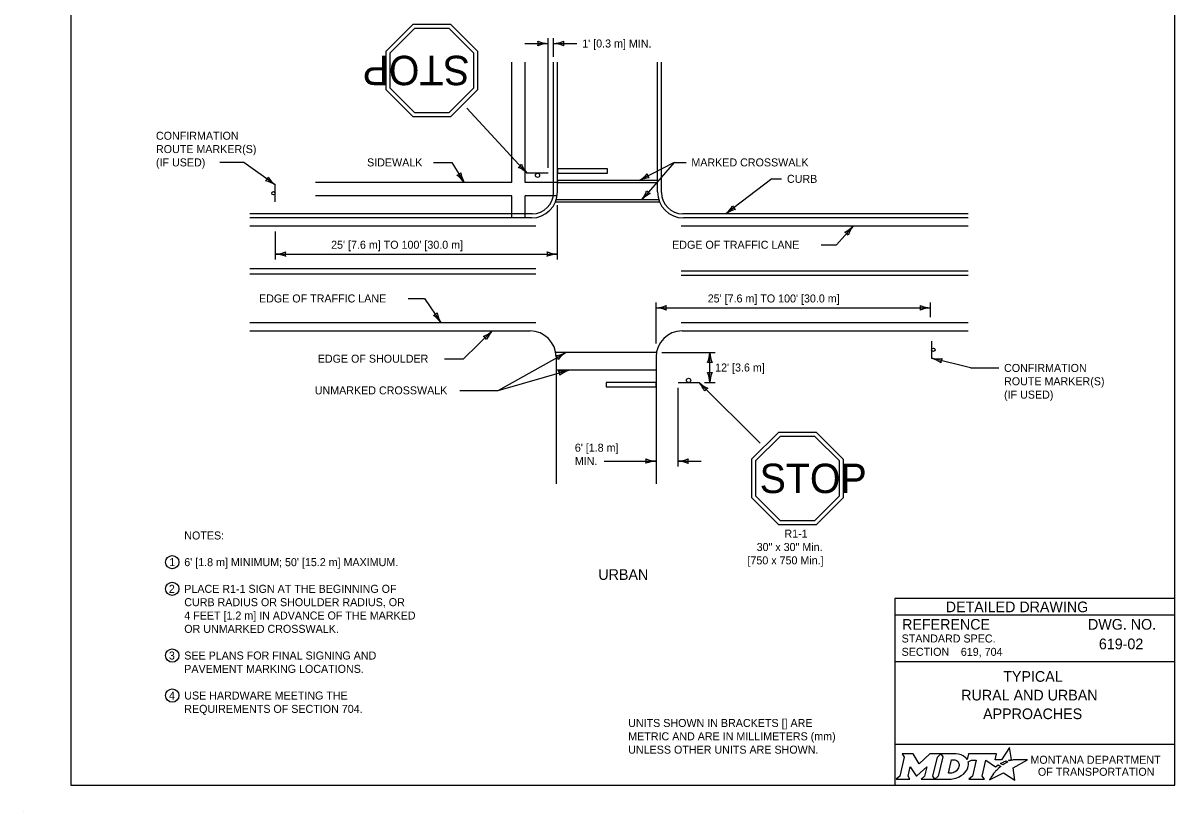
# Model space of a CAD drawing. Extents: x 49991.4 to 50021, y 49987.6 to 50011.4.
# Drawn here: x 49999.98 to 50008.61, y 49999.86 to 50005.78 of the extents above; entities that cross this region are included whole.
import ezdxf

# ---------------------------------------------------------------- set-up
doc = ezdxf.new("R2010")
doc.units = 0
for name, color, linetype in [('Level 1', 7, 'Continuous'), ('Level 2', 7, 'Continuous'), ('Level 3', 7, 'Continuous')]:
    doc.layers.add(name, color=color, linetype=linetype)

# ---------------------------------------------------------------- blocks, each defined once
blk = doc.blocks.new('ARR')
at = {"layer": 'Level 3'}
for centre, radius, start, end in [((1.5, 37), 37.1, 247.4737, 267.6572), ((-21.4, 0), 9.13, 342.1565, 17.8788), ((1.9, -38.8), 38.8, 92.845, 112.0948)]:
    blk.add_arc(centre, radius, start, end, dxfattribs=at)
blk = doc.blocks.new('ARROW')
at = {"layer": 'Level 3', "xscale": 0.9999534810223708, "yscale": 0.999953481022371, "rotation": -0.017609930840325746}
blk.add_blockref('ARR', (-0.0303, -0.0431), dxfattribs=at)

msp = doc.modelspace()

# ---------------------------------------------------------------- linework, layer by layer
at = {"layer": 'Level 1'}
for p, q in [((50002.8988, 50005.7665), (50002.697, 50005.5647)), ((50002.9113, 50005.7365), (50002.727, 50005.5522)), ((50003.1846, 50005.7665), (50002.8988, 50005.7665)), ((50003.172, 50005.7365), (50002.9113, 50005.7365)), ((50003.172, 50005.7365), (50003.3563, 50005.5522)), ((50003.1846, 50005.7665), (50003.3863, 50005.5648)), ((50002.697, 50005.5647), (50002.697, 50005.2791)), ((50003.3863, 50005.279), (50003.3863, 50005.5648)), ((50002.727, 50005.5522), (50002.727, 50005.2915)), ((50003.3563, 50005.2915), (50003.3563, 50005.5522)), ((50003.6422, 50004.5813), (50003.6422, 50005.4852)), ((50003.7422, 50004.5813), (50003.7422, 50005.4852)), ((50003.9542, 50004.5066), (50003.9542, 50005.4852)), ((50003.9842, 50004.512), (50003.9842, 50005.4852)), ((50004.7342, 50004.5119), (50004.7342, 50005.4851)), ((50004.7642, 50004.5066), (50004.7642, 50005.4852)), ((50002.8989, 50005.0772), (50002.697, 50005.2791)), ((50002.9113, 50005.1072), (50002.727, 50005.2915)), ((50003.172, 50005.1072), (50003.3563, 50005.2915)), ((50003.1845, 50005.0772), (50003.3863, 50005.279)), ((50002.8989, 50005.0772), (50003.1845, 50005.0772)), ((50002.9113, 50005.1072), (50003.172, 50005.1072)), ((50003.9137, 50004.6516), (50003.7555, 50004.6516)), ((50004.3592, 50004.6836), (50003.9842, 50004.6836)), ((50003.9842, 50004.6836), (50003.9842, 50004.6516)), ((50003.9842, 50004.6516), (50004.3592, 50004.6516)), ((50004.3592, 50004.6516), (50004.3592, 50004.6836)), ((50001.8667, 50004.4381), (50001.8667, 50004.5647)), ((50003.6422, 50004.5813), (50002.1694, 50004.5813)), ((50003.9842, 50004.5813), (50003.7422, 50004.5813)), ((50004.7342, 50004.5963), (50003.9842, 50004.5963)), ((50003.9842, 50004.5963), (50003.9842, 50004.5813)), ((50003.9842, 50004.5813), (50004.7342, 50004.5813)), ((50004.7342, 50004.5813), (50004.7342, 50004.5963)), ((50003.6422, 50004.4813), (50002.1694, 50004.4813)), ((50003.6422, 50004.3167), (50003.6422, 50004.4813)), ((50003.7422, 50004.3167), (50003.7422, 50004.4813)), ((50003.9818, 50004.4813), (50003.7422, 50004.4813)), ((50003.9692, 50004.4367), (50004.7493, 50004.4367)), ((50004.7438, 50004.4517), (50003.9747, 50004.4517)), ((50003.7942, 50004.3466), (50001.6775, 50004.3466)), ((50007.0628, 50004.3466), (50004.9242, 50004.3466)), ((50003.7889, 50004.3167), (50001.6775, 50004.3167)), ((50007.0628, 50004.3166), (50004.9296, 50004.3166)), ((50003.8222, 50004.2541), (50001.6775, 50004.2541)), ((50007.0628, 50004.2541), (50004.9128, 50004.2541)), ((50003.8222, 50003.9347), (50001.6775, 50003.9347)), ((50007.0628, 50003.9178), (50004.9128, 50003.9178)), ((50003.8222, 50003.8954), (50001.6775, 50003.8954)), ((50007.0628, 50003.8856), (50004.9128, 50003.8856)), ((50001.6775, 50003.5316), (50003.8222, 50003.5316)), ((50004.9128, 50003.5316), (50007.0628, 50003.5316)), ((50001.6775, 50003.4691), (50003.7783, 50003.4691)), ((50004.919, 50003.4691), (50007.0628, 50003.4691)), ((50006.79, 50003.3913), (50006.79, 50003.2648)), ((50004.7266, 50003.3073), (50003.9708, 50003.3073)), ((50003.9737, 50003.2738), (50003.9737, 50002.323)), ((50004.7237, 50003.2738), (50004.7237, 50002.3229)), ((50004.7237, 50003.1738), (50003.9737, 50003.1738)), ((50004.7237, 50003.0822), (50004.3487, 50003.0823)), ((50004.3487, 50003.0823), (50004.3487, 50003.0503)), ((50004.3487, 50003.0503), (50004.7237, 50003.0502)), ((50004.7237, 50003.0502), (50004.7237, 50003.0822)), ((50004.8882, 50003.0822), (50005.0465, 50003.0822)), ((50005.6415, 50002.7081), (50005.4397, 50002.5063)), ((50005.9271, 50002.7081), (50005.6415, 50002.7081)), ((50005.9271, 50002.7081), (50006.129, 50002.5062)), ((50005.654, 50002.6781), (50005.4697, 50002.4938)), ((50005.9147, 50002.6781), (50005.654, 50002.6781)), ((50005.9147, 50002.6781), (50006.099, 50002.4938)), ((50005.4397, 50002.5063), (50005.4397, 50002.2205)), ((50005.4697, 50002.4938), (50005.4697, 50002.2331)), ((50006.099, 50002.2331), (50006.099, 50002.4938)), ((50006.129, 50002.2206), (50006.129, 50002.5062)), ((50005.6414, 50002.0188), (50005.4397, 50002.2205)), ((50005.654, 50002.0488), (50005.4697, 50002.2331)), ((50005.9147, 50002.0488), (50006.099, 50002.2331)), ((50005.9272, 50002.0188), (50006.129, 50002.2206)), ((50005.6414, 50002.0188), (50005.9272, 50002.0188)), ((50005.654, 50002.0488), (50005.9147, 50002.0488)), ((49999.9766, 49999.8624), (49999.9766, 49999.8624))]:
    msp.add_line(p, q, dxfattribs=at)
msp.add_lwpolyline([(50008.6146, 50011.2628), (50000.3356, 50011.2628), (50000.3356, 50000.0624), (50008.6146, 50000.0624)], close=True, dxfattribs=at)
for centre, radius in [((50003.8346, 50004.6358), 0.0158), ((50001.854, 50004.5013), 0.0127), ((50006.8027, 50003.3281), 0.0127), ((50004.9673, 50003.0981), 0.0159)]:
    msp.add_circle(centre, radius, dxfattribs=at)
for centre, radius, start, end in [((50003.7889, 50004.512), 0.1953, 270, 0), ((50003.7942, 50004.5066), 0.16, 270, 0), ((50003.7889, 50004.5119), 0.1953, 337.34235, 342.03572), ((50004.9296, 50004.5119), 0.1953, 180, 270), ((50004.9296, 50004.5119), 0.1953, 197.96428, 202.65765), ((50004.9242, 50004.5066), 0.16, 180, 270), ((50003.7783, 50003.2738), 0.1953, 0, 90), ((50004.919, 50003.2738), 0.1953, 90, 180)]:
    msp.add_arc(centre, radius, start, end, dxfattribs=at)
at = {"layer": 'Level 2'}
for p, q in [((50008.6146, 50001.4624), (50006.5146, 50001.4624)), ((50006.5146, 50001.4624), (50006.5146, 50000.0624)), ((50008.6146, 50001.3374), (50006.5146, 50001.3374)), ((50008.2507, 50001.1223), (50008.2507, 50001.1223)), ((50008.6146, 50000.9874), (50006.5146, 50000.9874)), ((50007.0089, 50001.0629), (50007.0089, 50001.0629)), ((50007.5646, 50000.7383), (50007.5646, 50000.7383)), ((50008.6146, 50000.3693), (50006.5146, 50000.3693))]:
    msp.add_line(p, q, dxfattribs=at)
for points in [[(50006.5701, 50000.2974), (50006.5842, 50000.274), (50006.5507, 50000.1307), (50006.525, 50000.1082), (50006.6266, 50000.1082), (50006.6131, 50000.131), (50006.6293, 50000.2011), (50006.673, 50000.1321), (50006.6783, 50000.1321), (50006.7534, 50000.2016), (50006.737, 50000.1305), (50006.7123, 50000.1085), (50006.8139, 50000.1085), (50006.8001, 50000.1318), (50006.8333, 50000.2742)], [(50006.8333, 50000.2742), (50006.8586, 50000.2974), (50006.7762, 50000.2974), (50006.6966, 50000.2244), (50006.6521, 50000.2971), (50006.5701, 50000.2974)], [(50006.9722, 50000.2974), (50006.8586, 50000.2974), (50006.8733, 50000.2745), (50006.8394, 50000.1307), (50006.8139, 50000.1085), (50006.9245, 50000.1085)], [(50007.3771, 50000.2447), (50007.3668, 50000.2503), (50007.3784, 50000.2531), (50007.39, 50000.2551), (50007.3726, 50000.3452), (50007.3131, 50000.2539), (50007.2658, 50000.2532), (50007.2761, 50000.2973), (50007.0669, 50000.2974), (50007.0568, 50000.2549), (50007.051, 50000.2632)], [(50006.9962, 50000.2107), (50006.995, 50000.2026), (50006.9918, 50000.1933), (50006.9876, 50000.1851), (50006.982, 50000.1776), (50006.9755, 50000.1707), (50006.9676, 50000.1644), (50006.9593, 50000.1597), (50006.9502, 50000.1558), (50006.9411, 50000.1535), (50006.9319, 50000.1526), (50006.916, 50000.1526), (50006.9396, 50000.2526), (50006.9556, 50000.2526), (50006.9632, 50000.252), (50006.9708, 50000.2501), (50006.9774, 50000.2471), (50006.9835, 50000.2429), (50006.9883, 50000.2379), (50006.992, 50000.2319), (50006.9947, 50000.2257), (50006.9963, 50000.2183), (50006.9963, 50000.2153), (50006.9962, 50000.2107)], [(50007.0636, 50000.2383), (50007.0882, 50000.2514), (50007.1251, 50000.2514), (50007.0965, 50000.1309), (50007.069, 50000.1082), (50007.1852, 50000.1082), (50007.1682, 50000.1311), (50007.1964, 50000.2513), (50007.2677, 50000.1996), (50007.2888, 50000.2147), (50007.3085, 50000.2038)], [(50007.2527, 50000.1479), (50007.2374, 50000.1235), (50007.2327, 50000.116), (50007.2269, 50000.1074), (50007.2246, 50000.1031), (50007.3299, 50000.1562), (50007.4138, 50000.1011), (50007.4007, 50000.1938), (50007.5076, 50000.2522), (50007.4583, 50000.253), (50007.4282, 50000.2534), (50007.4074, 50000.2537), (50007.4006, 50000.2522), (50007.3957, 50000.251), (50007.3873, 50000.2487), (50007.3771, 50000.2447)], [(50007.3267, 50000.2171), (50007.3243, 50000.2154), (50007.306, 50000.225), (50007.3163, 50000.2307), (50007.3204, 50000.2329), (50007.329, 50000.2369), (50007.3347, 50000.2395), (50007.3426, 50000.2425), (50007.3499, 50000.2452), (50007.3617, 50000.2378), (50007.3577, 50000.2357), (50007.3531, 50000.2332), (50007.3489, 50000.231), (50007.3439, 50000.2281), (50007.342, 50000.227), (50007.3393, 50000.2254), (50007.3368, 50000.224), (50007.3345, 50000.2224), (50007.3319, 50000.2206), (50007.3292, 50000.2188), (50007.3267, 50000.2171)], [(50006.9702, 50000.1158), (50006.9786, 50000.1184), (50006.9916, 50000.1238), (50007.012, 50000.1348)], [(50007.2666, 50000.164), (50007.2666, 50000.164)]]:
    msp.add_lwpolyline(points, dxfattribs=at)
for centre in [(50001.0956, 50001.7353), (50001.0956, 50001.5353), (50001.0956, 50001.0353), (50001.0956, 50000.7353)]:
    msp.add_circle(centre, 0.05, dxfattribs=at)
for centre, radius, start, end in [((50006.9953, 50000.219), 0.0709, 339.53292, 15.85821), ((50006.9513, 50000.2363), 0.1183, 300.91025, 339.13831)]:
    msp.add_arc(centre, radius, start, end, dxfattribs=at)
for centre, major_axis, ratio, start_param, end_param in [((50006.9701, 50000.25), (0.0834, -0.0037), 0.568097, 0.61298, 1.570796), ((50007.0257, 50000.2573), (0.0361, -0.0295), 0.469099, 1.225588, 1.570796), ((50007.2974, 50000.1941), (-0.0112, -0.0097), 0.021651, 3.157348, 6.283185), ((50006.9248, 50000.2568), (0, 0.1484), 0.987302, 3.139398, 3.456847), ((50007.2597, 50000.1559), (-0.00694, -0.00806), 0.008222, 0, 3.137361), ((50007.2764, 50000.1742), (-0.0098, -0.0102), 0.016458, 3.141593, 6.279097)]:
    msp.add_ellipse(centre, major_axis=major_axis, ratio=ratio, start_param=start_param, end_param=end_param, dxfattribs=at)
at = {"layer": 'Level 3'}
for p, q in [((50003.9137, 50004.6916), (50003.9137, 50005.664)), ((50003.9542, 50005.5252), (50003.9542, 50005.664)), ((50003.7403, 50005.624), (50003.9137, 50005.624)), ((50003.9542, 50005.624), (50004.13, 50005.624)), ((50003.3036, 50005.1398), (50003.7555, 50004.6516)), ((50001.6329, 50004.7325), (50001.4529, 50004.7325)), ((50001.8667, 50004.5647), (50001.6329, 50004.7325)), ((50003.0534, 50004.7325), (50003.1908, 50004.7325)), ((50003.1908, 50004.7325), (50003.285, 50004.5813)), ((50004.8589, 50004.7325), (50004.5967, 50004.5963)), ((50004.8589, 50004.7325), (50004.6158, 50004.4517)), ((50004.8589, 50004.7325), (50004.9483, 50004.7325)), ((50005.5905, 50004.6093), (50005.2475, 50004.3466)), ((50005.5905, 50004.6093), (50005.665, 50004.6093)), ((50003.9842, 50004.0051), (50003.9842, 50004.412)), ((50001.8687, 50004.0051), (50001.8687, 50004.2141)), ((50006.076, 50004.1151), (50006.2014, 50004.2541)), ((50005.9623, 50004.1151), (50006.076, 50004.1151)), ((50001.8687, 50004.0451), (50003.9842, 50004.0451)), ((50002.8643, 50003.7124), (50002.9877, 50003.7124)), ((50002.9877, 50003.7124), (50003.1098, 50003.5316)), ((50004.7237, 50003.3738), (50004.7237, 50003.6824)), ((50006.7817, 50003.5723), (50006.7817, 50003.6824)), ((50004.7237, 50003.6424), (50006.7817, 50003.6424)), ((50003.2796, 50003.2608), (50003.4954, 50003.4691)), ((50003.1364, 50003.2608), (50003.2796, 50003.2608)), ((50003.5402, 50003.0224), (50004.0483, 50003.3073)), ((50004.7666, 50003.3073), (50005.1665, 50003.3073)), ((50005.1265, 50003.0822), (50005.1265, 50003.3073)), ((50007.0816, 50003.1915), (50006.79, 50003.2648)), ((50003.5402, 50003.0224), (50004.0701, 50003.1738)), ((50007.0816, 50003.1915), (50007.2931, 50003.1915)), ((50005.0465, 50003.0822), (50005.5048, 50002.6279)), ((50005.0865, 50003.0822), (50005.1665, 50003.0822)), ((50003.2531, 50003.0224), (50003.5402, 50003.0224)), ((50004.8876, 50003.0422), (50004.8876, 50002.4527)), ((50004.3339, 50002.4935), (50004.7237, 50002.4935)), ((50004.8876, 50002.4927), (50005.061, 50002.4927))]:
    msp.add_line(p, q, dxfattribs=at)
for centre, radius, start, end in [((50003.9229, 50005.8461), 0.2223, 247.45601, 267.63952), ((50003.7855, 50005.624), 0.0548, 342.13882, 17.86118), ((50003.9252, 50005.3913), 0.233, 92.82731, 112.07716), ((50003.9427, 50005.8567), 0.233, 272.82731, 292.07716), ((50003.945, 50005.4019), 0.2223, 67.45601, 87.63952), ((50004.0824, 50005.624), 0.0548, 162.13882, 197.86118), ((50003.6667, 50004.7441), 0.0548, 295.96133, 331.68369), ((50003.5956, 50004.4822), 0.233, 46.64982, 65.89967), ((50003.9221, 50004.7988), 0.2223, 201.27852, 221.46203), ((50001.7625, 50004.6395), 0.0548, 306.47458, 342.19694), ((50002.0037, 50004.7398), 0.2223, 211.79177, 231.97528), ((50003.2172, 50004.6901), 0.0548, 284.05672, 319.77908), ((50003.0935, 50004.4485), 0.233, 34.74521, 53.99506), ((50003.4784, 50004.691), 0.2223, 189.37391, 209.55742), ((50001.7404, 50004.3689), 0.233, 57.16307, 76.41292), ((50005.0969, 50004.5244), 0.233, 310.27394, 329.52379), ((50005.3753, 50004.1647), 0.2223, 104.90264, 125.08615), ((50005.3493, 50004.4246), 0.0548, 199.58545, 235.30781), ((50006.0426, 50004.4097), 0.2223, 295.39808, 315.58159), ((50006.1155, 50004.1589), 0.0548, 30.08089, 65.80325), ((50006.3819, 50004.1067), 0.233, 140.76938, 160.01923), ((50001.8572, 50004.2778), 0.233, 272.82731, 292.07716), ((50001.8595, 50003.823), 0.2223, 67.45601, 87.63952), ((50001.9969, 50004.0451), 0.0548, 162.13882, 197.86118), ((50003.9934, 50004.2672), 0.2223, 247.45601, 267.63952), ((50003.856, 50004.0451), 0.0548, 342.13882, 17.86118), ((50003.9957, 50003.8124), 0.233, 92.82731, 112.07716), ((50004.7122, 50003.8751), 0.233, 272.82731, 292.07716), ((50004.8519, 50003.6424), 0.0548, 162.13882, 197.86118), ((50006.7909, 50003.8645), 0.2223, 247.45601, 267.63952), ((50006.6535, 50003.6424), 0.0548, 342.13882, 17.86118), ((50003.0386, 50003.6382), 0.0548, 285.86814, 321.5905), ((50002.9226, 50003.3928), 0.233, 36.55663, 55.80648), ((50003.2996, 50003.6473), 0.2223, 191.18533, 211.36884), ((50004.7145, 50003.4203), 0.2223, 67.45601, 87.63952), ((50006.7932, 50003.4097), 0.233, 92.82731, 112.07716), ((50003.3477, 50003.6352), 0.2223, 291.44896, 311.63247), ((50003.4031, 50003.38), 0.0548, 26.13177, 61.85413), ((50003.6653, 50003.3096), 0.233, 136.82026, 156.07011), ((50003.9476, 50003.5055), 0.2223, 276.7357, 296.91921), ((50003.9365, 50003.2446), 0.0548, 11.41851, 47.14087), ((50004.1721, 50003.1099), 0.233, 122.107, 141.35685), ((50004.9044, 50003.3165), 0.2223, 337.45601, 357.63952), ((50005.1265, 50003.1791), 0.0548, 72.13882, 107.86118), ((50005.3592, 50003.3188), 0.233, 182.82731, 202.07716), ((50006.7238, 50003.0526), 0.2223, 52.49735, 72.68085), ((50006.839, 50003.4926), 0.233, 257.86865, 277.1185), ((50006.9139, 50003.2317), 0.0548, 147.18015, 182.90252), ((50004.0179, 50003.3899), 0.2223, 263.40141, 283.58492), ((50003.9468, 50003.1386), 0.0548, 358.08422, 33.80658), ((50004.1451, 50002.9532), 0.233, 108.77271, 128.02256), ((50005.1265, 50003.2104), 0.0548, 252.13882, 287.86118), ((50004.8938, 50003.0707), 0.233, 2.82731, 22.07716), ((50005.3486, 50003.073), 0.2223, 157.45601, 177.63952), ((50004.882, 50002.9326), 0.2223, 22.09386, 42.27737), ((50005.204, 50003.2539), 0.233, 227.46516, 246.71501), ((50005.1366, 50002.991), 0.0548, 116.77667, 152.49903), ((50004.7329, 50002.7156), 0.2223, 247.45601, 267.63952), ((50004.5955, 50002.4935), 0.0548, 342.13882, 17.86118), ((50004.7352, 50002.2608), 0.233, 92.82731, 112.07716)]:
    msp.add_arc(centre, radius, start, end, dxfattribs=at)

# ---------------------------------------------------------------- block references
for p, xscale, yscale, rotation in [((50004.5967, 50004.596), 0.005999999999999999, 0.005999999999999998, -152.55038653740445), ((50004.6159, 50004.4514), 0.005999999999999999, 0.006, -130.88411671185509), ((50004.8874, 50002.4924), 0.006, 0.006, 180)]:
    msp.add_blockref('ARROW', p, dxfattribs=dict(at, xscale=xscale, yscale=yscale, rotation=rotation))

# ---------------------------------------------------------------- texts
at = {"layer": 'Level 1'}
for rotation, p in [(180, (50003.3256, 50005.5321)), (360, (50005.5004, 50002.2532))]:
    msp.add_text('STOP', height=0.2205, rotation=rotation, dxfattribs=at).set_placement(p)
at = {"layer": 'Level 2'}
for s, height, p in [("1' [0.3 m] MIN.", 0.06, (50004.17, 50005.594)), ('CONFIRMATION', 0.06, (50000.9735, 50004.9025)), ('ROUTE MARKER(S)', 0.06, (50000.9735, 50004.8025)), ('(IF USED)', 0.06, (50000.9735, 50004.7025)), ('SIDEWALK', 0.06, (50002.5566, 50004.7025)), ('MARKED CROSSWALK', 0.06, (50004.9883, 50004.7025)), ('CURB', 0.06, (50005.705, 50004.5793)), ("25' [7.6 m] TO 100' [30.0 m]", 0.06, (50002.2867, 50004.0851)), ('EDGE OF TRAFFIC LANE', 0.06, (50004.8441, 50004.0851)), ('EDGE OF TRAFFIC LANE', 0.06, (50001.7461, 50003.6824)), ("25' [7.6 m] TO 100' [30.0 m]", 0.06, (50005.1108, 50003.6824)), ('EDGE OF SHOULDER', 0.06, (50002.1867, 50003.2308)), ("12' [3.6 m]", 0.06, (50005.1665, 50003.1648)), ('CONFIRMATION', 0.06, (50007.3331, 50003.1615)), ('UNMARKED CROSSWALK', 0.06, (50002.1642, 50002.9934)), ('ROUTE MARKER(S)', 0.06, (50007.3331, 50003.0615)), ('(IF USED)', 0.06, (50007.3331, 50002.9615)), ("6' [1.8 m]", 0.06, (50004.1143, 50002.5635)), ('MIN.', 0.06, (50004.1143, 50002.4635)), ('NOTES:', 0.06, (50001.1856, 50001.9053)), ('R1-1', 0.06, (50005.686, 50001.9188)), ('30" x 30" Min.', 0.06, (50005.4779, 50001.8188)), ('1', 0.06, (50001.0729, 50001.7053)), ("6' [1.8 m] MINIMUM; 50' [15.2 m] MAXIMUM.", 0.06, (50001.1856, 50001.7053)), ('[750 x 750 Min.]', 0.06, (50005.4089, 50001.7188)), ('URBAN', 0.08, (50004.2906, 50001.6024)), ('2', 0.06, (50001.0704, 50001.5053)), ('PLACE R1-1 SIGN AT THE BEGINNING OF', 0.06, (50001.1856, 50001.5053)), ('CURB RADIUS OR SHOULDER RADIUS, OR', 0.06, (50001.1856, 50001.4053)), ('DETAILED DRAWING', 0.0799, (50006.8956, 50001.3599)), ('4 FEET [1.2 m] IN ADVANCE OF THE MARKED', 0.06, (50001.1856, 50001.3053)), ('OR UNMARKED CROSSWALK.', 0.06, (50001.1856, 50001.2053)), ('REFERENCE', 0.08, (50006.5682, 50001.229)), ('DWG. NO.', 0.08, (50007.9624, 50001.229)), ('STANDARD SPEC.', 0.06, (50006.5649, 50001.133)), ('619-02', 0.08, (50008.0441, 50001.0823)), ('3', 0.06, (50001.0704, 50001.0053)), ('SEE PLANS FOR FINAL SIGNING AND', 0.06, (50001.1856, 50001.0053)), ('SECTION', 0.06, (50006.5649, 50001.033)), ('619, 704', 0.06, (50007.0089, 50001.0329)), ('PAVEMENT MARKING LOCATIONS.', 0.06, (50001.1856, 50000.9053)), ('TYPICAL', 0.08, (50007.3268, 50000.8383)), ('4', 0.06, (50001.0716, 50000.7053)), ('USE HARDWARE MEETING THE ', 0.06, (50001.1856, 50000.7053)), ('RURAL AND URBAN', 0.08, (50007.0121, 50000.6983)), ('REQUIREMENTS OF SECTION 704.', 0.06, (50001.1856, 50000.6053)), ('APPROACHES', 0.08, (50007.1758, 50000.5583)), ('UNITS SHOWN IN BRACKETS [] ARE ', 0.06, (50004.5146, 50000.4996)), ('METRIC AND ARE IN MILLIMETERS (mm) ', 0.06, (50004.5146, 50000.3996)), ('UNLESS OTHER UNITS ARE SHOWN.', 0.06, (50004.5146, 50000.2996)), ('MONTANA DEPARTMENT', 0.06, (50007.5308, 50000.2236)), ('OF TRANSPORTATION', 0.06, (50007.587, 50000.1336))]:
    msp.add_text(s, height=height, dxfattribs=at).set_placement(p)

doc.saveas('drawing.dxf')
